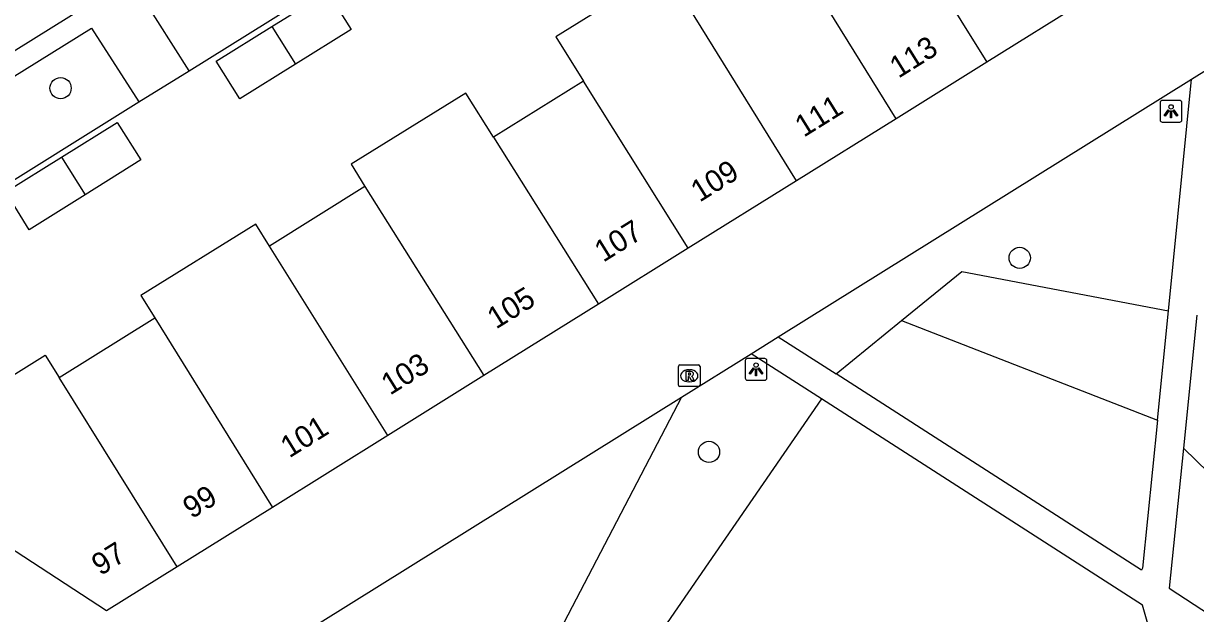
# Model space of a CAD drawing. Extents: x 155275 to 156263, y 382654 to 383635.
# Drawn here: x 155440.7 to 155494.7, y 383001 to 383028.1 of the extents above; entities that cross this region are included whole.
import ezdxf

# ---------------------------------------------------------------- set-up
doc = ezdxf.new("R2010")
doc.units = 0
for name, color, linetype in [('IMGEO_Boom', 7, 'Continuous'), ('IMGEO_Groenvoorziening', 7, 'Continuous'), ('IMGEO_Lichtpunt', 7, 'Continuous'), ('IMGEO_Pand', 7, 'Continuous'), ('IMGEO_Pand_nummerreeks', 7, 'Continuous'), ('IMGEO_Rijbaan_lokaal_halfverhard', 7, 'Continuous'), ('IMGEO_Rioolput', 7, 'Continuous'), ('IMGEO_Voetpad_halfverhard', 7, 'Continuous'), ('IMGEO_Voetpad_open', 7, 'Continuous')]:
    doc.layers.add(name, color=color, linetype=linetype)

msp = doc.modelspace()

# ---------------------------------------------------------------- linework, layer by layer
at = {"layer": 'IMGEO_Boom'}
for centre in [(155442.438, 383025.157), (155486.568, 383017.35), (155472.272, 383008.423)]:
    msp.add_circle(centre, 0.489, dxfattribs=at)
at = {"layer": 'IMGEO_Groenvoorziening'}
for points in [[(155448.352, 383025.956), (155455.714, 383030.549)], [(155438.501, 383019.821), (155446.037, 383024.535)], [(155481.126, 383014.46), (155483.906, 383016.722), (155493.409, 383014.915)], [(155478.116, 383012.01), (155481.126, 383014.46)], [(155481.126, 383014.46), (155492.906, 383009.887)], [(155471.008, 383010.94), (155465.23, 382999.846)], [(155477.449, 383010.857), (155469.091, 382998.733)], [(155504.224, 382991.304), (155500.971, 383001.91), (155494.101, 383008.6)]]:
    msp.add_lwpolyline(points, dxfattribs=at)
at = {"layer": 'IMGEO_Lichtpunt'}
for p, q in [((155493.03, 383024.5), (155493.03, 383023.693)), ((155493.03, 383024.5), (155493.03, 383023.693)), ((155493.932, 383024.595), (155493.124, 383024.595)), ((155493.932, 383024.595), (155493.124, 383024.595)), ((155494.026, 383023.693), (155494.026, 383024.5)), ((155494.026, 383023.693), (155494.026, 383024.5)), ((155493.124, 383023.599), (155493.932, 383023.599)), ((155493.124, 383023.599), (155493.932, 383023.599)), ((155473.94, 383012.621), (155473.94, 383011.814)), ((155473.94, 383012.621), (155473.94, 383011.814)), ((155474.842, 383012.716), (155474.034, 383012.716)), ((155474.842, 383012.716), (155474.034, 383012.716)), ((155474.936, 383011.814), (155474.936, 383012.621)), ((155474.936, 383011.814), (155474.936, 383012.621)), ((155474.034, 383011.72), (155474.842, 383011.72)), ((155474.034, 383011.72), (155474.842, 383011.72))]:
    msp.add_line(p, q, dxfattribs=at)
for points in [[(155493.404, 383024.164), (155493.443, 383024.136), (155493.255, 383023.874), (155493.217, 383023.901), (155493.404, 383024.164)], [(155493.506, 383024.116), (155493.553, 383024.116), (155493.553, 383023.794), (155493.506, 383023.794), (155493.506, 383024.116)], [(155493.616, 383024.136), (155493.654, 383024.163), (155493.841, 383023.901), (155493.802, 383023.873), (155493.616, 383024.136)], [(155474.314, 383012.285), (155474.353, 383012.257), (155474.165, 383011.995), (155474.127, 383012.022), (155474.314, 383012.285)], [(155474.416, 383012.237), (155474.463, 383012.237), (155474.463, 383011.915), (155474.416, 383011.915), (155474.416, 383012.237)], [(155474.526, 383012.257), (155474.564, 383012.284), (155474.751, 383012.022), (155474.712, 383011.994), (155474.526, 383012.257)]]:
    msp.add_lwpolyline(points, dxfattribs=at)
for centre in [(155493.529, 383024.298), (155474.439, 383012.419)]:
    msp.add_circle(centre, 0.0994, dxfattribs=at)
for centre, start, end in [((155493.124, 383024.5), 90, 180), ((155493.124, 383024.5), 90, 180), ((155493.932, 383024.5), 0, 90), ((155493.932, 383024.5), 0, 90), ((155493.124, 383023.693), 180, 270), ((155493.124, 383023.693), 180, 270), ((155493.932, 383023.693), 270, 0), ((155493.932, 383023.693), 270, 360), ((155474.034, 383012.621), 90, 180), ((155474.034, 383012.621), 90, 180), ((155474.842, 383012.621), 0, 90), ((155474.842, 383012.621), 0, 90), ((155474.034, 383011.814), 180, 270), ((155474.034, 383011.814), 180, 270), ((155474.842, 383011.814), 270, 0), ((155474.842, 383011.814), 270, 360)]:
    msp.add_arc(centre, 0.0946, start, end, dxfattribs=at)
at = {"layer": 'IMGEO_Pand'}
for points in [[(155480.273, 383034.039), (155485.061, 383026.36)], [(155480.881, 383023.754), (155476.114, 383031.449)], [(155470.882, 383029.64), (155470.254, 383030.655), (155465.222, 383027.519), (155466.496, 383025.487)], [(155476.293, 383020.894), (155470.882, 383029.64)], [(155452.166, 383027.993), (155454.723, 383029.588), (155455.812, 383027.861), (155453.246, 383026.261)], [(155489.64, 383029.215), (155485.061, 383026.36)], [(155453.246, 383026.261), (155450.681, 383024.66), (155449.6, 383026.393), (155452.166, 383027.993)], [(155452.166, 383027.993), (155453.246, 383026.261)], [(155485.061, 383026.36), (155480.881, 383023.754)], [(155466.496, 383025.487), (155462.364, 383022.898)], [(155471.319, 383017.794), (155466.496, 383025.487)], [(155462.364, 383022.898), (155461.091, 383024.929), (155455.803, 383021.653), (155456.441, 383020.638)], [(155480.881, 383023.754), (155476.293, 383020.894)], [(155442.486, 383021.982), (155445.044, 383023.576), (155446.136, 383021.853), (155443.568, 383020.25)], [(155462.364, 383022.898), (155467.181, 383015.213)], [(155443.568, 383020.25), (155441, 383018.646), (155439.919, 383020.382), (155442.486, 383021.982)], [(155442.486, 383021.982), (155443.568, 383020.25)], [(155456.441, 383020.638), (155452.051, 383017.893)], [(155456.441, 383020.638), (155461.914, 383011.93)], [(155476.293, 383020.894), (155471.319, 383017.794)], [(155452.051, 383017.893), (155451.42, 383018.902), (155446.138, 383015.62), (155446.773, 383014.595)], [(155457.501, 383009.179), (155452.051, 383017.893)], [(155471.319, 383017.794), (155467.181, 383015.213)], [(155467.181, 383015.213), (155461.914, 383011.93)], [(155442.371, 383011.852), (155446.773, 383014.595)], [(155446.773, 383014.595), (155452.182, 383005.863)], [(155436.175, 383006.569), (155438.523, 383008.032), (155437.249, 383010.076), (155441.735, 383012.872), (155442.371, 383011.852)], [(155447.806, 383003.135), (155442.371, 383011.852)], [(155461.914, 383011.93), (155457.501, 383009.179)], [(155457.501, 383009.179), (155452.182, 383005.863)], [(155447.806, 383003.135), (155444.556, 383001.109), (155436.175, 383006.569)], [(155452.182, 383005.863), (155447.806, 383003.135)]]:
    msp.add_lwpolyline(points, dxfattribs=at)
at = {"layer": 'IMGEO_Rijbaan_lokaal_halfverhard'}
msp.add_lwpolyline([(155505.376, 383067.393), (155425.36, 383017.563), (155408.379, 383006.989)], dxfattribs=at)
at = {"layer": 'IMGEO_Rioolput'}
for p, q in [((155470.938, 383012.424), (155471.79, 383012.424)), ((155470.863, 383011.498), (155470.863, 383012.35)), ((155471.351, 383012.204), (155471.376, 383012.204)), ((155471.864, 383012.35), (155471.864, 383011.498)), ((155471.79, 383011.424), (155470.938, 383011.424)), ((155471.374, 383011.644), (155471.349, 383011.644))]:
    msp.add_line(p, q, dxfattribs=at)
for points in [[(155470.938, 383012.424), (155471.79, 383012.424)], [(155470.863, 383011.498), (155470.863, 383012.35)], [(155471.452, 383012.122), (155471.2, 383012.124), (155471.2, 383011.724)], [(155471.2, 383011.724), (155471.324, 383011.724), (155471.324, 383011.886), (155471.335, 383011.886)], [(155471.378, 383012.043), (155471.324, 383012.043), (155471.324, 383011.962)], [(155471.324, 383011.962), (155471.376, 383011.962)], [(155471.382, 383011.857), (155471.453, 383011.724), (155471.593, 383011.724), (155471.528, 383011.85)], [(155471.864, 383012.35), (155471.864, 383011.498)], [(155471.79, 383011.424), (155470.938, 383011.424)]]:
    msp.add_lwpolyline(points, dxfattribs=at)
for centre, radius, start, end in [((155470.94, 383012.348), 0.0765, 91.552, 178.448), ((155470.94, 383012.348), 0.0765, 91.552, 178.448), ((155471.788, 383012.348), 0.0765, 1.552, 88.448), ((155471.788, 383012.348), 0.0765, 1.552, 88.448), ((155471.334, 383011.833), 0.0533, 26.0293, 88.6989), ((155471.36, 383012.151), 0.19, 274.7715, 282.9687), ((155471.384, 383011.947), 0.0964, 77.0061, 93.1865), ((155471.398, 383012.004), 0.0378, 276.6634, 79.6772), ((155471.451, 383012.012), 0.109, 350.3612, 89.416), ((155471.449, 383012.012), 0.112, 277.5842, 350.9817), ((155471.433, 383011.797), 0.108, 29.5134, 73.7905), ((155470.94, 383011.5), 0.0765, 181.552, 268.448), ((155470.94, 383011.5), 0.0765, 181.552, 268.448), ((155471.788, 383011.5), 0.0765, 271.552, 358.448), ((155471.788, 383011.5), 0.0765, 271.552, 358.448)]:
    msp.add_arc(centre, radius, start, end, dxfattribs=at)
for centre, major_axis, ratio, start_param, end_param in [((155471.35, 383011.924), (-0.387, 0.002), 0.722429, 4.712389, 7.853982), ((155471.375, 383011.924), (-0.39, 0.002), 0.717154, 1.570796, 4.712389)]:
    msp.add_ellipse(centre, major_axis=major_axis, ratio=ratio, start_param=start_param, end_param=end_param, dxfattribs=at)
at = {"layer": 'IMGEO_Voetpad_halfverhard'}
for points in [[(155493.409, 383014.915), (155494.475, 383025.569)], [(155492.906, 383009.887), (155493.409, 383014.915)], [(155494.716, 383014.712), (155494.101, 383008.6)], [(155475.461, 383013.715), (155478.116, 383012.01)], [(155477.449, 383010.857), (155474.212, 383012.937)], [(155492.906, 383009.887), (155492.224, 383003.067), (155492.176, 383002.979), (155478.116, 383012.01)], [(155463.557, 382990.705), (155474.436, 382976.649), (155487.381, 382965.751), (155491.188, 382966.102), (155498.409, 382979.644), (155492.224, 383001.364), (155477.449, 383010.857)], [(155494.101, 383008.6), (155493.451, 383002.148), (155497.251, 382999.662), (155498.161, 382993.595), (155504.224, 382991.304)]]:
    msp.add_lwpolyline(points, dxfattribs=at)
at = {"layer": 'IMGEO_Voetpad_open'}
for points in [[(155448.352, 383025.956), (155446.198, 383029.375), (155453.6, 383033.984), (155455.714, 383030.549)], [(155438.501, 383019.821), (155436.429, 383023.299), (155443.859, 383027.925), (155446.037, 383024.535)], [(155494.475, 383025.569), (155496.669, 383026.937), (155499.11, 383023.363)], [(155446.037, 383024.535), (155448.352, 383025.956)], [(155475.461, 383013.715), (155494.475, 383025.569)], [(155474.212, 383012.937), (155475.461, 383013.715)], [(155471.008, 383010.94), (155474.212, 383012.937)], [(155448.793, 382997.09), (155471.008, 383010.94)]]:
    msp.add_lwpolyline(points, dxfattribs=at)

# ---------------------------------------------------------------- texts
at = {"layer": 'IMGEO_Pand_nummerreeks'}
for s, p in [('113', (155480.991, 383025.59)), ('111', (155476.634, 383022.874)), ('109', (155471.841, 383019.886)), ('107', (155467.408, 383017.122)), ('105', (155462.474, 383014.046)), ('103', (155457.597, 383011.006)), ('101', (155452.964, 383008.118)), ('99', (155448.47, 383005.317)), ('97', (155444.271, 383002.699))]:
    msp.add_text(s, height=1, rotation=31.9424, dxfattribs=at).set_placement(p)

doc.saveas('drawing.dxf')
